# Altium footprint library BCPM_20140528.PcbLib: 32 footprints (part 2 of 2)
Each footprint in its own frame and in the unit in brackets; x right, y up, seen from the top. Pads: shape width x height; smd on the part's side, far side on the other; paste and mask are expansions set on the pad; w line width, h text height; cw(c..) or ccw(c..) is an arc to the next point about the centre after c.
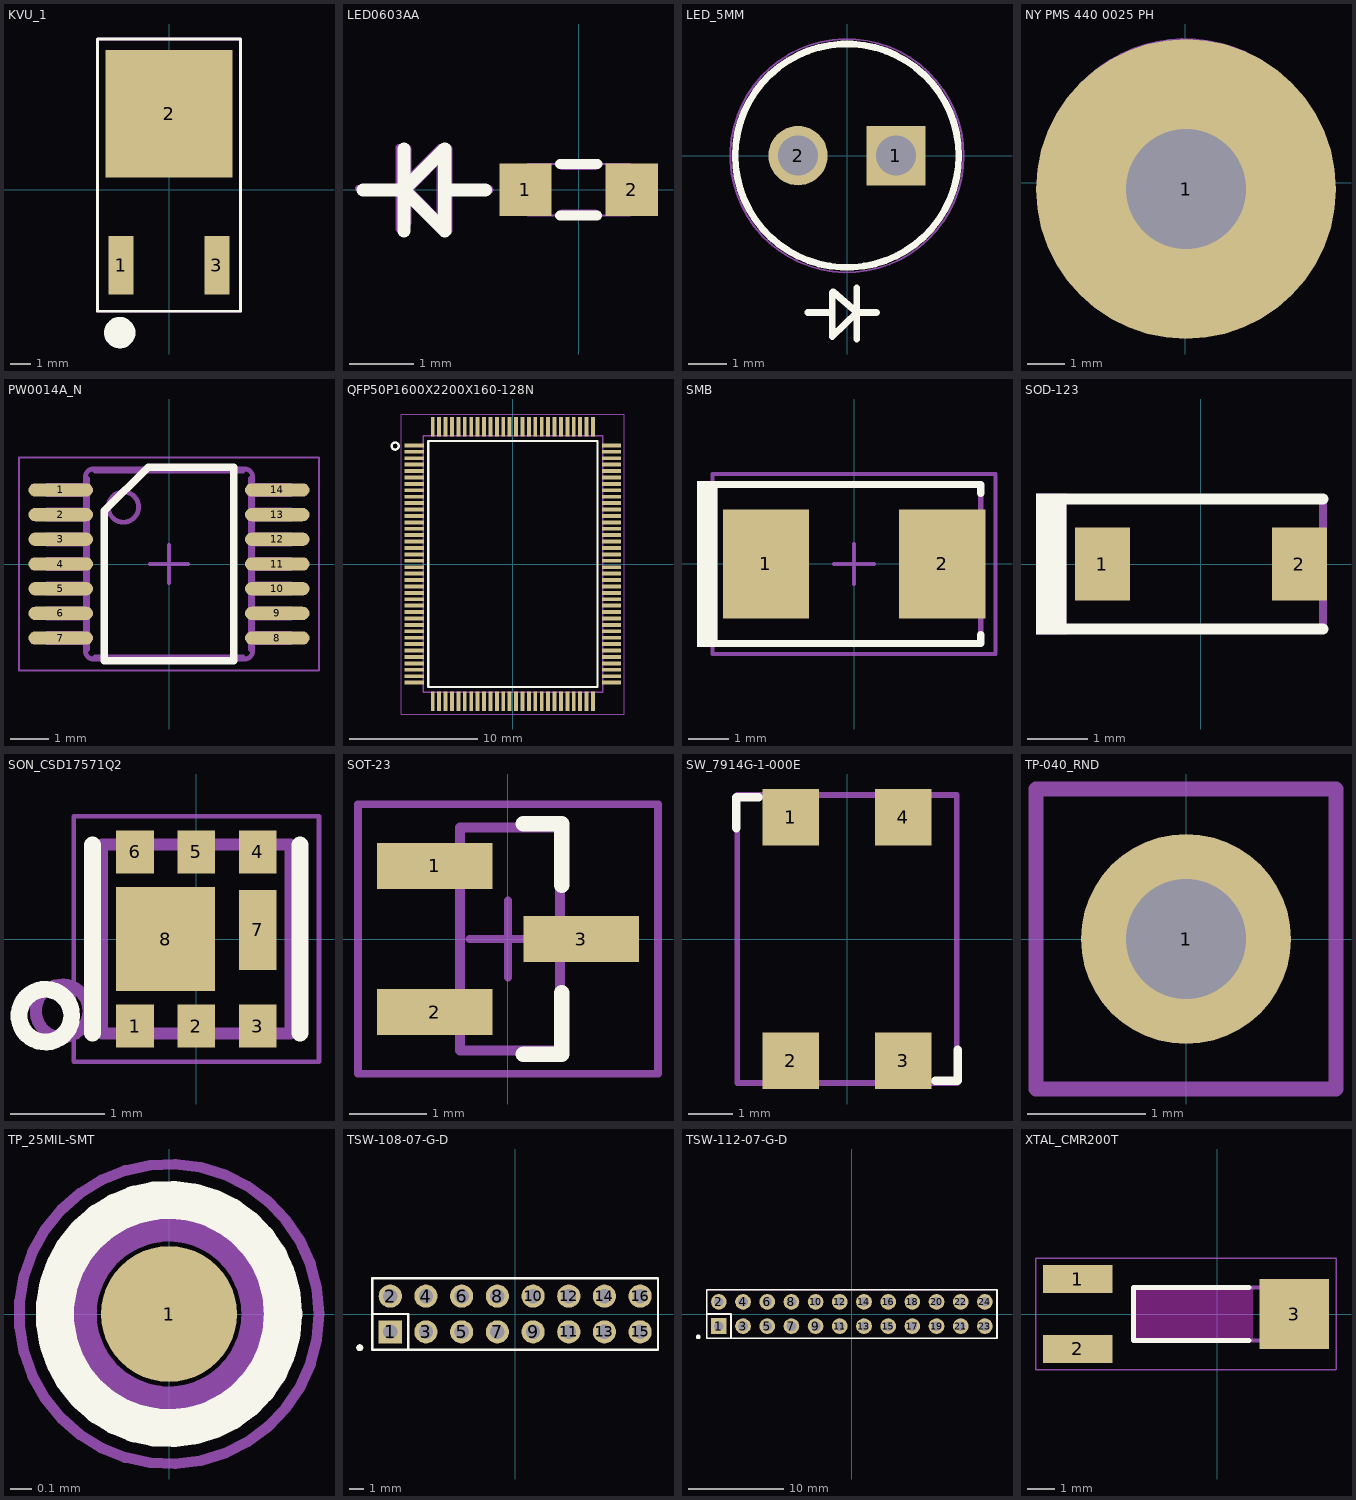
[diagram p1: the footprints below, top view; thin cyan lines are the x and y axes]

## KVU_1 [mm]
height 2.39
pads (3):
  rect 1.2x2.8 smd: 1(-2.29,-3.635) 3(2.29,-3.635)
  rect 6.096x6.096 smd: 2(0,3.635)
Top Overlay:
  circle w0.889: c-2.362,-6.858 r0.305
  lines w0.127: -3.429,-5.841 3.429,-5.841 3.429,7.216 -3.429,7.216 -3.429,-5.841
Mechanical 5:
  lines w0.127: -3.429,-5.841 -3.429,7.216 3.429,7.216 3.429,-5.841 -3.429,-5.841
  text ".Designator" at 0.381,-0.381 h0.76

## LED0603AA [mil]
height 35.43
pads (2):
  rect 32x32 smd: 1(-32.48,0) 2(32.48,0)
Top Overlay:
  lines w6: -11.42,-15.75 11.42,-15.75 ; -11.42,15.75 11.42,15.75
  lines w8: -131.79,-0.04 -106.79,-0.04 ; -106.79,-25.04 -106.79,24.96 ; -81.79,-0.04 -56.79,-0.04 ; -106.79,-0.04 -81.79,24.96 -81.79,-25.04 -106.79,-0.04
Mechanical 5:
  lines w6: -130,0 -105,0 ; -105,-20 -105,25 ; -80,0 -55,0 ; -10,-15 10,-15 ; -10,15 10,15 ; -105,0 -80,-25 -80,25 -105,0
  text ".Designator" at 25,79 h60
Mechanical 15:
  lines w1: -31.5,-15.75 31.5,-15.75 31.5,15.75 -31.5,15.75 -31.5,-15.75
  lines w3.94: -134.79,0.96 -109.79,0.96 ; -109.79,-24.04 -109.79,25.96 ; -84.79,0.96 -59.79,0.96 ; -109.79,0.96 -84.79,25.96 -84.79,-24.04 -109.79,0.96

## LED_5MM [mm] "LED, 5MM, RED, TH"
height 9
pads (2):
  rect 1.54x1.54 / inner round 1.54 / far side rect 1.54x1.54 hole 1.04: 1(1.27,0)
  round 1.54 hole 1.04: 2(-1.27,0)
Top Overlay:
  circle w0.178: c0,0 r2.9
  lines w0.178: -1.019,-4.064 -0.381,-4.064 ; -0.381,-4.696 -0.381,-3.556 ; -0.375,-4.677 0.254,-4.064 -0.363,-3.529 ; 0.254,-4.756 0.254,-3.429 ; 0.266,-4.064 0.762,-4.064
  text ".Designator" at 0.254,3.302 h1.02
Bottom Overlay:
  lines w0.178: -2.899,0.001 ccw(c0.001,0.001) -2.51,-1.449 ; -2.51,1.451 cw(c0.001,0.001) -1.449,2.513 ; -1.449,-2.51 ccw(c0.001,0.001) 0.001,-2.899 ; 0.001,2.901 cw(c0.001,0.001) 1.451,2.513 ; 1.451,-2.51 ccw(c0.001,0.001) 2.513,-1.449 ; 2.513,1.451 cw(c0.001,0.001) 2.901,0.001
Mechanical 5:
  circle w0.127: c0,0 r2.9
  lines w0.127: -1.019,-4.064 -0.381,-4.064 ; -0.381,-4.696 -0.381,-3.529 ; -0.375,-4.677 0.254,-4.064 -0.363,-3.529 ; 0.254,-4.756 0.254,-3.556 ; 0.266,-4.064 0.762,-4.064
  text ".Designator" at -0.635,0.889 h0.76
Mechanical 15:
  circle w0.05: c0,0 r3.027
3D body: height 9, standoff 0, extent -2.9,-2.9 2.9,2.9

## NY PMS 440 0025 PH [mm] "4-40 nylon screw and mounting hole"
height 1.905
pads (1):
  round 8 hole 3.2: 1(0.021,-0.172)
Mechanical 5:
  circle w0.127: c0,0 r3.789
  text ".Designator" at -1.524,-0.508 h1.02
3D body: height 2.69, standoff -8.74, extent -3.302,-3.3 3.296,3.3

## PW0014A_N [mm] "TSOP, 14-Leads, Body 5x4.4mm, Pitch 0.65mm, IPC Medium Density"
height 1.2
pads (14):
  oval 1.7x0.35 smd: 1(-2.85,1.95) 2(-2.85,1.3) 3(-2.85,0.65) 4(-2.85,0) 5(-2.85,-0.65) 6(-2.85,-1.3) 7(-2.85,-1.95) 8(2.85,-1.95) 9(2.85,-1.3) 10(2.85,-0.65) 11(2.85,0) 12(2.85,0.65) 13(2.85,1.3) 14(2.85,1.95)
Top Overlay:
  lines w0.2: -1.7,-2.55 1.7,-2.55 1.7,2.55 -0.55,2.55 -1.7,1.4 -1.7,-2.55
Mechanical 5:
  drawing of 182 lines, arcs and shapes, not listed
  text ".Designator" at -0.762,-0.508 h0.76
Mechanical 15:
  lines w0.05: -3.95,-2.8 -3.95,2.8 3.95,2.8 3.95,-2.8 -3.95,-2.8
  lines w0.1: -0.5,0 0.5,0 ; 0,-0.5 0,0.5
3D body: height 0.98, standoff -0.02, extent -3.21,-2.5 3.21,2.5

## QFP50P1600X2200X160-128N [mm] "IC, 0.5MM PITCH, QFP-128P"
height 1.6
pads (128):
  rect 1.5x0.3 smd: 1(-7.7,9.25) 2(-7.7,8.75) 3(-7.7,8.25) 4(-7.7,7.75) 5(-7.7,7.25) 6(-7.7,6.75) 7(-7.7,6.25) 8(-7.7,5.75) 9(-7.7,5.25) 10(-7.7,4.75) 11(-7.7,4.25) 12(-7.7,3.75) 13(-7.7,3.25) 14(-7.7,2.75) 15(-7.7,2.25) 16(-7.7,1.75) 17(-7.7,1.25) 18(-7.7,0.75) 19(-7.7,0.25) 20(-7.7,-0.25) 21(-7.7,-0.75) 22(-7.7,-1.25) 23(-7.7,-1.75) 24(-7.7,-2.25) 25(-7.7,-2.75) 26(-7.7,-3.25) 27(-7.7,-3.75) 28(-7.7,-4.25) 29(-7.7,-4.75) 30(-7.7,-5.25) 31(-7.7,-5.75) 32(-7.7,-6.25) 33(-7.7,-6.75) 34(-7.7,-7.25) 35(-7.7,-7.75) 36(-7.7,-8.25) 37(-7.7,-8.75) 38(-7.7,-9.25) 65(7.7,-9.25) 66(7.7,-8.75) 67(7.7,-8.25) 68(7.7,-7.75) 69(7.7,-7.25) 70(7.7,-6.75) 71(7.7,-6.25) 72(7.7,-5.75) 73(7.7,-5.25) 74(7.7,-4.75) 75(7.7,-4.25) 76(7.7,-3.75) 77(7.7,-3.25) 78(7.7,-2.75) 79(7.7,-2.25) 80(7.7,-1.75) 81(7.7,-1.25) 82(7.7,-0.75) 83(7.7,-0.25) 84(7.7,0.25) 85(7.7,0.75) 86(7.7,1.25) 87(7.7,1.75) 88(7.7,2.25) 89(7.7,2.75) 90(7.7,3.25) 91(7.7,3.75) 92(7.7,4.25) 93(7.7,4.75) 94(7.7,5.25) 95(7.7,5.75) 96(7.7,6.25) 97(7.7,6.75) 98(7.7,7.25) 99(7.7,7.75) 100(7.7,8.25) 101(7.7,8.75) 102(7.7,9.25)
  rect 0.3x1.5 smd: 39(-6.25,-10.7) 40(-5.75,-10.7) 41(-5.25,-10.7) 42(-4.75,-10.7) 43(-4.25,-10.7) 44(-3.75,-10.7) 45(-3.25,-10.7) 46(-2.75,-10.7) 47(-2.25,-10.7) 48(-1.75,-10.7) 49(-1.25,-10.7) 50(-0.75,-10.7) 51(-0.25,-10.7) 52(0.25,-10.7) 53(0.75,-10.7) 54(1.25,-10.7) 55(1.75,-10.7) 56(2.25,-10.7) 57(2.75,-10.7) 58(3.25,-10.7) 59(3.75,-10.7) 60(4.25,-10.7) 61(4.75,-10.7) 62(5.25,-10.7) 63(5.75,-10.7) 64(6.25,-10.7) 103(6.25,10.7) 104(5.75,10.7) 105(5.25,10.7) 106(4.75,10.7) 107(4.25,10.7) 108(3.75,10.7) 109(3.25,10.7) 110(2.75,10.7) 111(2.25,10.7) 112(1.75,10.7) 113(1.25,10.7) 114(0.75,10.7) 115(0.25,10.7) 116(-0.25,10.7) 117(-0.75,10.7) 118(-1.25,10.7) 119(-1.75,10.7) 120(-2.25,10.7) 121(-2.75,10.7) 122(-3.25,10.7) 123(-3.75,10.7) 124(-4.25,10.7) 125(-4.75,10.7) 126(-5.25,10.7) 127(-5.75,10.7) 128(-6.25,10.7)
Top Overlay:
  circle w0.178: c-9.179,9.2 r0.279
  lines w0.178: -6.6,-9.6 6.6,-9.6 6.6,9.6 -6.6,9.6 -6.6,-9.6
  text ".Designator" at 1.473,-12.37 h1.02
Mechanical 5:
  circle w0.127: c-9.179,9.2 r0.279
  lines w0.127: -7,-10 7,-10 7,10 -7,10 -7,-10
  text ".Designator" at 0.254,0.254 h0.76
Mechanical 15:
  lines w0.05: -8.7,-11.7 -8.7,11.7 8.7,11.7 8.7,-11.7 -8.7,-11.7
3D body: height 1.6, standoff 0, extent -6.999,-9.999 6.999,9.999

## SMB [mm] "Molded Diode, 2-Leads, Body 5.4x3.6mm, IPC Medium Density, based on OnSemi component dimensions"
height 2.45
pads (2):
  rect 2.159x2.743 smd: 1(-2.21,0) 2(2.21,0)
Top Overlay:
  rectangle: -3.937,-2.083 -3.429,2.083
  lines w0.178: -3.607,-1.994 3.175,-1.994 3.175,-1.765 ; -3.607,1.994 3.175,1.994 3.175,1.765
Mechanical 5:
  rectangle: -3.937,-2.083 -3.429,2.083
  lines w0.127: -3.607,-1.994 3.175,-1.994 3.175,-1.765 3.175,1.765 3.175,1.994 -3.607,1.994
  text ".Designator" at 0.254,-0.508 h0.76
Mechanical 15:
  lines w0.1: -0.5,0 0.5,0 ; 0,-0.5 0,0.5 ; -3.55,-2.25 -3.55,2.25 3.55,2.25 3.55,-2.25 -3.55,-2.25
3D body: height 2.32, standoff 0.02, extent -2.7,-1.8 2.7,1.8

## SOD-123 [mm] "On Semi recommended land pattern"
height 1.35
pads (2):
  rect 0.915x1.22 smd: 1(-1.637,0) 2(1.637,0)
Top Overlay:
  rectangle: -2.741,-1.168 -2.233,1.168
  lines w0.178: -2.413,-1.079 2.032,-1.079 ; -2.413,1.079 2.032,1.079
Mechanical 5:
  rectangle: -2.741,-1.168 -2.233,1.168
  lines w0.127: -2.413,-1.079 2.032,-1.079 2.032,1.079 -2.413,1.079
  text ".Designator" at -1.956,-0.33 h0.76
3D body: height 1.35, standoff 0, extent -1.932,-0.9 1.932,0.9

## SON_CSD17571Q2 [mm] "SON, MOSFET, N-CH, 30V, 22A, SON 2X2 MM"
height 0.85
pads (8):
  rect 0.4x0.455 smd mask+0.038: 1(-0.65,-0.923) 2(0,-0.923) 5(0,0.923) 6(-0.65,0.923)
  rect 0.4x0.455 smd: 3(0.65,-0.923) 4(0.65,0.923)
  rect 0.4x0.85 smd mask+0.038: 7(0.65,0.096)
  rect 1.05x1.1 smd mask+0.038: 8(-0.325,0)
Top Overlay:
  circle w0.178: c-1.6,-0.813 r0.279
  lines w0.178: -1.1,-1 -1.1,1 ; 1.1,-1 1.1,1
  text ".Designator" at -1.397,0.127 h1.02
Mechanical 5:
  circle w0.127: c-1.422,-0.762 r0.279
  lines w0.127: -1,-1 -1,1 1,1 1,-1 -1,-1
  text ".Designator" at 0.381,-0.508 h0.76
Mechanical 15:
  lines w0.05: -1.3,-1.3 1.3,-1.3 1.3,1.3 -1.3,1.3 -1.3,-1.3
3D body: height 0.85, standoff 0, extent -1,-1 1,0.975

## SOT-23 [mm] "SOT23, 3-Leads, Body 2.9x1.3mm, Pitch 0.95mm, Lead Span 2.5mm, IPC Medium Density"
height 1.1
pads (3):
  rect 1.5x0.6 smd: 1(-0.95,0.95) 2(-0.95,-0.95) 3(0.95,0)
Top Overlay:
  lines w0.2: 0.2,-1.5 0.7,-1.5 0.7,-0.7 ; 0.2,1.5 0.7,1.5 0.7,0.7
Mechanical 5:
  lines w0.127: -1.16,-1.15 -0.625,-1.15 -0.625,-1.45 0.675,-1.45 0.675,-0.2 1.21,-0.2 1.21,0.2 0.675,0.2 0.675,1.45 -0.625,1.45 -0.625,1.15 -1.16,1.15 -1.16,0.75 -0.625,0.75 -0.625,-0.75 -1.16,-0.75 -1.16,-1.15
  text ".Designator" at 1.905,-1.905 h0.76
Mechanical 15:
  lines w0.1: -0.5,0 0.5,0 ; 0,-0.5 0,0.5 ; -1.95,-1.75 -1.95,1.75 1.95,1.75 1.95,-1.75 -1.95,-1.75
3D body: height 1, standoff 0, extent -1.16,-1.45 1.21,1.45

## SW_7914G-1-000E [mm] "BOURNS"
height 4.49
pads (4):
  rect 1.27x1.27 smd: 1(-1.27,2.75) 2(-1.27,-2.75) 3(1.27,-2.75) 4(1.27,2.75)
Top Overlay:
  lines w0.2: -2.5,2.5 -2.5,3.2 -2,3.2 ; 2,-3.2 2.5,-3.2 2.5,-2.5
Mechanical 5:
  lines w0.127: -2.48,-3.25 -2.48,3.25 2.48,3.25 2.48,-3.25 -2.48,-3.25
  text ".Designator" at -0.762,0.508 h0.76
3D body: height 2.54, standoff 0, extent -2.249,-2.499 2.249,2.499
3D body: height 4.49, standoff 2, extent -1.21,-1.21 1.21,1.21

## TP-040_RND [mil]
pads (1):
  round 70 / inner round 62 / far side round 62 hole 40: 1(0,0)
Mechanical 5:
  lines w5: -50,-50 -50,50 50,50 50,-50 -50,-50
  text ".Designator" at -47,-19 h60

## TP_25MIL-SMT [mm] "SMT, TESTPOINT"
pads (1):
  round 0.635 smd mask-0.064: 1(0,0)
Top Overlay:
  circle w0.178: c0,0 r0.533
  text ".Designator" at 1.067,-0.508 h1.02
Mechanical 5:
  circle w0.127: c0,0 r0.402
  text ".Designator" at 0.813,-0.381 h0.76
Mechanical 15:
  circle w0.05: c0,0 r0.7
3D body: height 0.05, standoff 0, extent -0.399,-0.401 0.402,0.401

## TSW-108-07-G-D [mm] "Samtec 100mil, 2x8, 230 mil above insulator"
height 8.382
pads (16):
  rect 1.65x1.65 hole 1.016 mask+0: 1(-8.89,-1.27)
  round 1.65 hole 1.016 mask+0: 2(-8.89,1.27) 3(-6.35,-1.27) 4(-6.35,1.27) 5(-3.81,-1.27) 6(-3.81,1.27) 7(-1.27,-1.27) 8(-1.27,1.27) 9(1.27,-1.27) 10(1.27,1.27) 11(3.81,-1.27) 12(3.81,1.27) 13(6.35,-1.27) 14(6.35,1.27) 15(8.89,-1.27) 16(8.89,1.27)
Top Overlay:
  circle w0.25: c-11.06,-2.4 r0.125
  lines w0.178: -10.16,0 -7.62,0 -7.62,-2.54 ; -10.16,-2.54 -10.16,2.54 10.16,2.54 10.16,-2.54 -10.16,-2.54
Mechanical 5:
  rectangle: -9.398,-1.778 -8.382,-0.762
  lines w0.127: -10.16,-2.54 10.16,-2.54 10.16,2.54 -10.16,2.54 -10.16,-2.54
  text ".Designator" at -1.454,0.381 h0.76
3D body: height 8.38, standoff -2.54, extent -10.16,-2.54 10.16,2.54

## TSW-112-07-G-D [mm] "Samtec 100mil, 2x12, 230 mil above insulator"
height 8.382
pads (24):
  rect 1.65x1.65 hole 1.016 mask+0: 1(-13.97,-1.27)
  round 1.65 hole 1.016 mask+0: 2(-13.97,1.27) 3(-11.43,-1.27) 4(-11.43,1.27) 5(-8.89,-1.27) 6(-8.89,1.27) 7(-6.35,-1.27) 8(-6.35,1.27) 9(-3.81,-1.27) 10(-3.81,1.27) 11(-1.27,-1.27) 12(-1.27,1.27) 13(1.27,-1.27) 14(1.27,1.27) 15(3.81,-1.27) 16(3.81,1.27) 17(6.35,-1.27) 18(6.35,1.27) 19(8.89,-1.27) 20(8.89,1.27) 21(11.43,-1.27) 22(11.43,1.27) 23(13.97,-1.27) 24(13.97,1.27)
Top Overlay:
  circle w0.25: c-16.14,-2.4 r0.125
  lines w0.178: -15.24,0 -12.7,0 -12.7,-2.54 ; -15.24,-2.54 -15.24,2.54 15.24,2.54 15.24,-2.54 -15.24,-2.54
Mechanical 5:
  rectangle: -14.478,-1.778 -13.462,-0.762
  lines w0.127: -15.24,-2.54 15.24,-2.54 15.24,2.54 -15.24,2.54 -15.24,-2.54
  text ".Designator" at 1.161,0.381 h0.76
3D body: height 8.38, standoff -2.54, extent -15.24,-2.54 15.24,2.54

## XTAL_CMR200T [mm] "XTAL, SMD, 3-PIN"
height 2
pads (3):
  rect 2.5x1 smd: 1(-5,1.25) 2(-5,-1.25)
  rect 2.5x2.5 smd: 3(2.75,0)
Top Layer keep-out:
  rectangle: -3.048,-0.946 1.272,0.954
Top Overlay:
  lines w0.178: 1.125,-0.95 -3,-0.95 -3,0.95 1.125,0.95
  text ".Designator" at 4.597,-0.127 h1.02
Mechanical 5:
  lines w0.127: -3,-0.95 3,-0.95 3,0.95 -3,0.95 -3,-0.95
  text ".Designator" at -0.254,-0.381 h0.76
Mechanical 15:
  lines w0.05: -6.5,-2 4.25,-2 4.25,2 -6.5,2 -6.5,-2
3D body: height 2, standoff 0, extent -3,-0.95 3,0.95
